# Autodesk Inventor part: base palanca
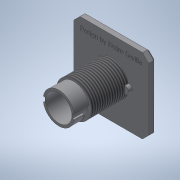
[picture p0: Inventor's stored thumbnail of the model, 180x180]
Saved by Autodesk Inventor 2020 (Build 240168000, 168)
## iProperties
Created: 2018-10
Part Number: base palanca
Material: Genérico
Document SubType Name: Modeling
Designer: Pedro
Density: 1 g/cm^3
Appearance: Por defecto
Author: Pedro
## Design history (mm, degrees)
sketch "Boceto1"
  geometry: L1 (-11.671, 10.819)-(48.329, 10.819); L2 (48.329, 10.819)-(48.329, -49.181); L3 (-11.671, 10.819)-(-11.671, -49.181); L4 (-11.671, -49.181)-(48.329, -49.181); C1 r 8 at (18.329, -19.181); 1 further point
  constraints: 8 end point, 1 centre point, 1 horizontal, 1 parallel, 1 perpendicular
extrude "Extrusión1" new body sketch "Boceto1" distance "d4" = 6; taper "d5" = 0 deg
sketch "Boceto2"
  geometry: L1 (-35.329, 36.181)-(-1.329, 36.181); L2 (-1.329, 36.181)-(-1.329, 2.181); L3 (-1.329, 2.181)-(-35.329, 2.181); L4 (-35.329, 2.181)-(-35.329, 36.181); C1 r 8 at (-18.329, 19.181) reference; 1 further point
  constraints: 8 end point, 2 parallel, 1 horizontal, 1 perpendicular
extrude "Extrusión2" join sketch "Boceto2" distance "d7" = 2; taper "d8" = 0 deg
chamfer "Chaflán1" distance "d9" = 3; stored, may be unused: second distance "d10" = 2, angle "d11" = 45 deg
chamfer "Chaflán2" distance "d12" = 5; stored, may be unused: second distance "d13" = 2, angle "d14" = 45 deg
chamfer "Chaflán3" distance "d15" = 2; stored, may be unused: second distance "d16" = 2, angle "d17" = 45 deg
chamfer "Chaflán4" distance "d18" = 2; stored, may be unused: second distance "d19" = 2, angle "d20" = 45 deg
sketch "Boceto3"
  geometry: L1 (-32.329, -16.181)-(-25.745, -16.181); L2 (-10.912, -16.181)-(-4.328, -16.181); L3 (-32.329, -22.181)-(-25.745, -22.181); L4 (-10.912, -22.181)-(-4.328, -22.181); C1 r 8 at (-18.329, -19.181) reference; A1 r 3 centre (-32.329, -19.181) between (-32.329, -16.181) and (-32.329, -22.181); A2 r 3 centre (-4.328, -19.181) between (-4.328, -22.181) and (-4.328, -16.181); A3 r 8 centre (-18.329, -19.181) between (-25.745, -16.181) and (-25.745, -22.181); A4 r 8 centre (-18.329, -19.181) between (-10.912, -22.181) and (-10.912, -16.181); 1 further point
  constraints: 8 end point, 8 point on circle, 4 centre point, 4 parallel, 2 tangent, 1 coincident
extrude "Extrusión3" join sketch "Boceto3" distance "d26" = 3; taper "d27" = 0 deg
sketch "Boceto4"
  geometry: C1 r 14 at (-18.329, -19.181); C2 r 10.5 at (-18.329, -19.181); A1 r 8 centre (-18.329, -19.181) between (-25.745, -22.181) and (-10.912, -22.181) reference; 1 further point
  constraints: 2 centre point, 2 coincident
  dimensions: "d28" = 28 diameter of C1; "d29" = 21 diameter of C2
extrude "Extrusión4" join sketch "Boceto4" distance "d30" = 30; taper "d31" = 0 deg
feature "Rosca1" dims "d35" = 10, "d36" = 0
sketch "Boceto8"
  geometry: L1 (-10.912, -16.181)-(-8.266, -16.181) reference; 4 further points
  constraints: 2 coincident, 6 other
extrude "Extrusión8" join sketch "Boceto8" distance "d49" = 9; taper "d50" = 0 deg
sketch "Boceto9"
  geometry: C1 r 10.5 at (0, 0); C2 r 4 at (0, 0); 1 further point
  constraints: 2 centre point, 1 coincident
extrude "Extrusión9" join sketch "Boceto9" distance "d52" = 3.5; taper "d53" = 0 deg
sketch "Boceto10"
  geometry: C1 r 4 at (0, 0); C2 r 5.5 at (0, 0); 1 further point
  constraints: 2 centre point, 1 coincident
  dimensions: "d54" = 11 diameter of C2
extrude "Extrusión10" join sketch "Boceto10" distance "d55" = 1.5; taper "d56" = 0 deg
sketch "Boceto12"
  geometry: L1 (8.959, -7.544)-(7.778, -7.778); L2 (7.311, -10.139)-(7.78, -7.776); L3 (-7.311, 10.139)-(-7.78, 7.776); L4 (-8.96, 7.543)-(-7.78, 7.776); L5 (10.817, 2)-(12.339, 2); L6 (8.959, -7.544)-(8.988, -6.341); L7 (-8.96, 7.543)-(-8.988, 6.342); L8 (-12.339, -2)-(-10.817, -2); C1 r 10.5 at (0, 0); A1 r 12.5 centre (0, 0) between (12.339, 2) and (-7.311, 10.139); A2 r 12.5 centre (0, 0) between (-12.339, -2) and (7.311, -10.139); A3 r 11 centre (0, 0) between (8.988, -6.341) and (10.817, 2); A4 r 11 centre (0, 0) between (-8.988, 6.342) and (-10.817, -2); A5 r 11 centre (0, 0) between (7.778, -7.778) and (7.78, -7.776); 4 further points
  constraints: 16 end point, 10 point on circle, 6 centre point, 2 coincident
extrude "Extrusión11" join sketch "Boceto12" distance "d61" = 4; taper "d62" = 0 deg
sketch "Boceto13"
  geometry: L1 (-10.817, -2)-(-12.339, -2) reference; L2 (-12.339, -2)-(-10.817, -2); L3 (-10.817, 2)-(-12.339, 2); L4 (12.339, 2)-(10.817, 2); L5 (10.817, -2)-(12.339, -2); C1 r 10.5 at (0, 0); A1 r 12.5 centre (0, 0) between (-12.339, -2) and (7.311, -10.139) reference; A2 r 11 centre (0, 0) between (10.817, -2) and (10.817, 2); A3 r 11 centre (0, 0) between (-10.817, 2) and (-10.817, -2); A4 r 12.5 centre (0, 0) between (-12.339, -2) and (12.339, -2); A5 r 12.5 centre (0, 0) between (12.339, 2) and (-12.339, 2); 2 further points
  constraints: 8 end point, 8 point on circle, 5 centre point, 3 equal length, 2 coincident, 1 point on line
extrude "Extrusión12" join sketch "Boceto13" distance "d66" = 8; taper "d67" = 0 deg
sketch "Boceto14"
  geometry: L1 (-43.326, 5.218)-(12.386, 5.218); L2 (12.386, 5.218)-(12.386, -2.76); L3 (12.386, -2.76)-(-43.326, -2.76); L4 (-43.326, -2.76)-(-43.326, 5.218); 1 further point
  constraints: 2 other
extrude "Extrusión13" cut sketch "Boceto14" distance "d68" = 1; taper "d69" = 0 deg
node "Sólido1"
other parameters: "d37" = 2, "d38" = 2, "d58" = 25, "d63" = 25, "d65" = 22
